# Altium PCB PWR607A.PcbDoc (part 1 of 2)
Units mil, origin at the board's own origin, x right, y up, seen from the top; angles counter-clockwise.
Board outline 5200 x 2850 mil, 4 copper layers (Top Layer, MidLayer1, MidLayer2, Bottom Layer), stack 61.6 mil thick; 153 components, 65 nets, 324 pads, 227 vias.
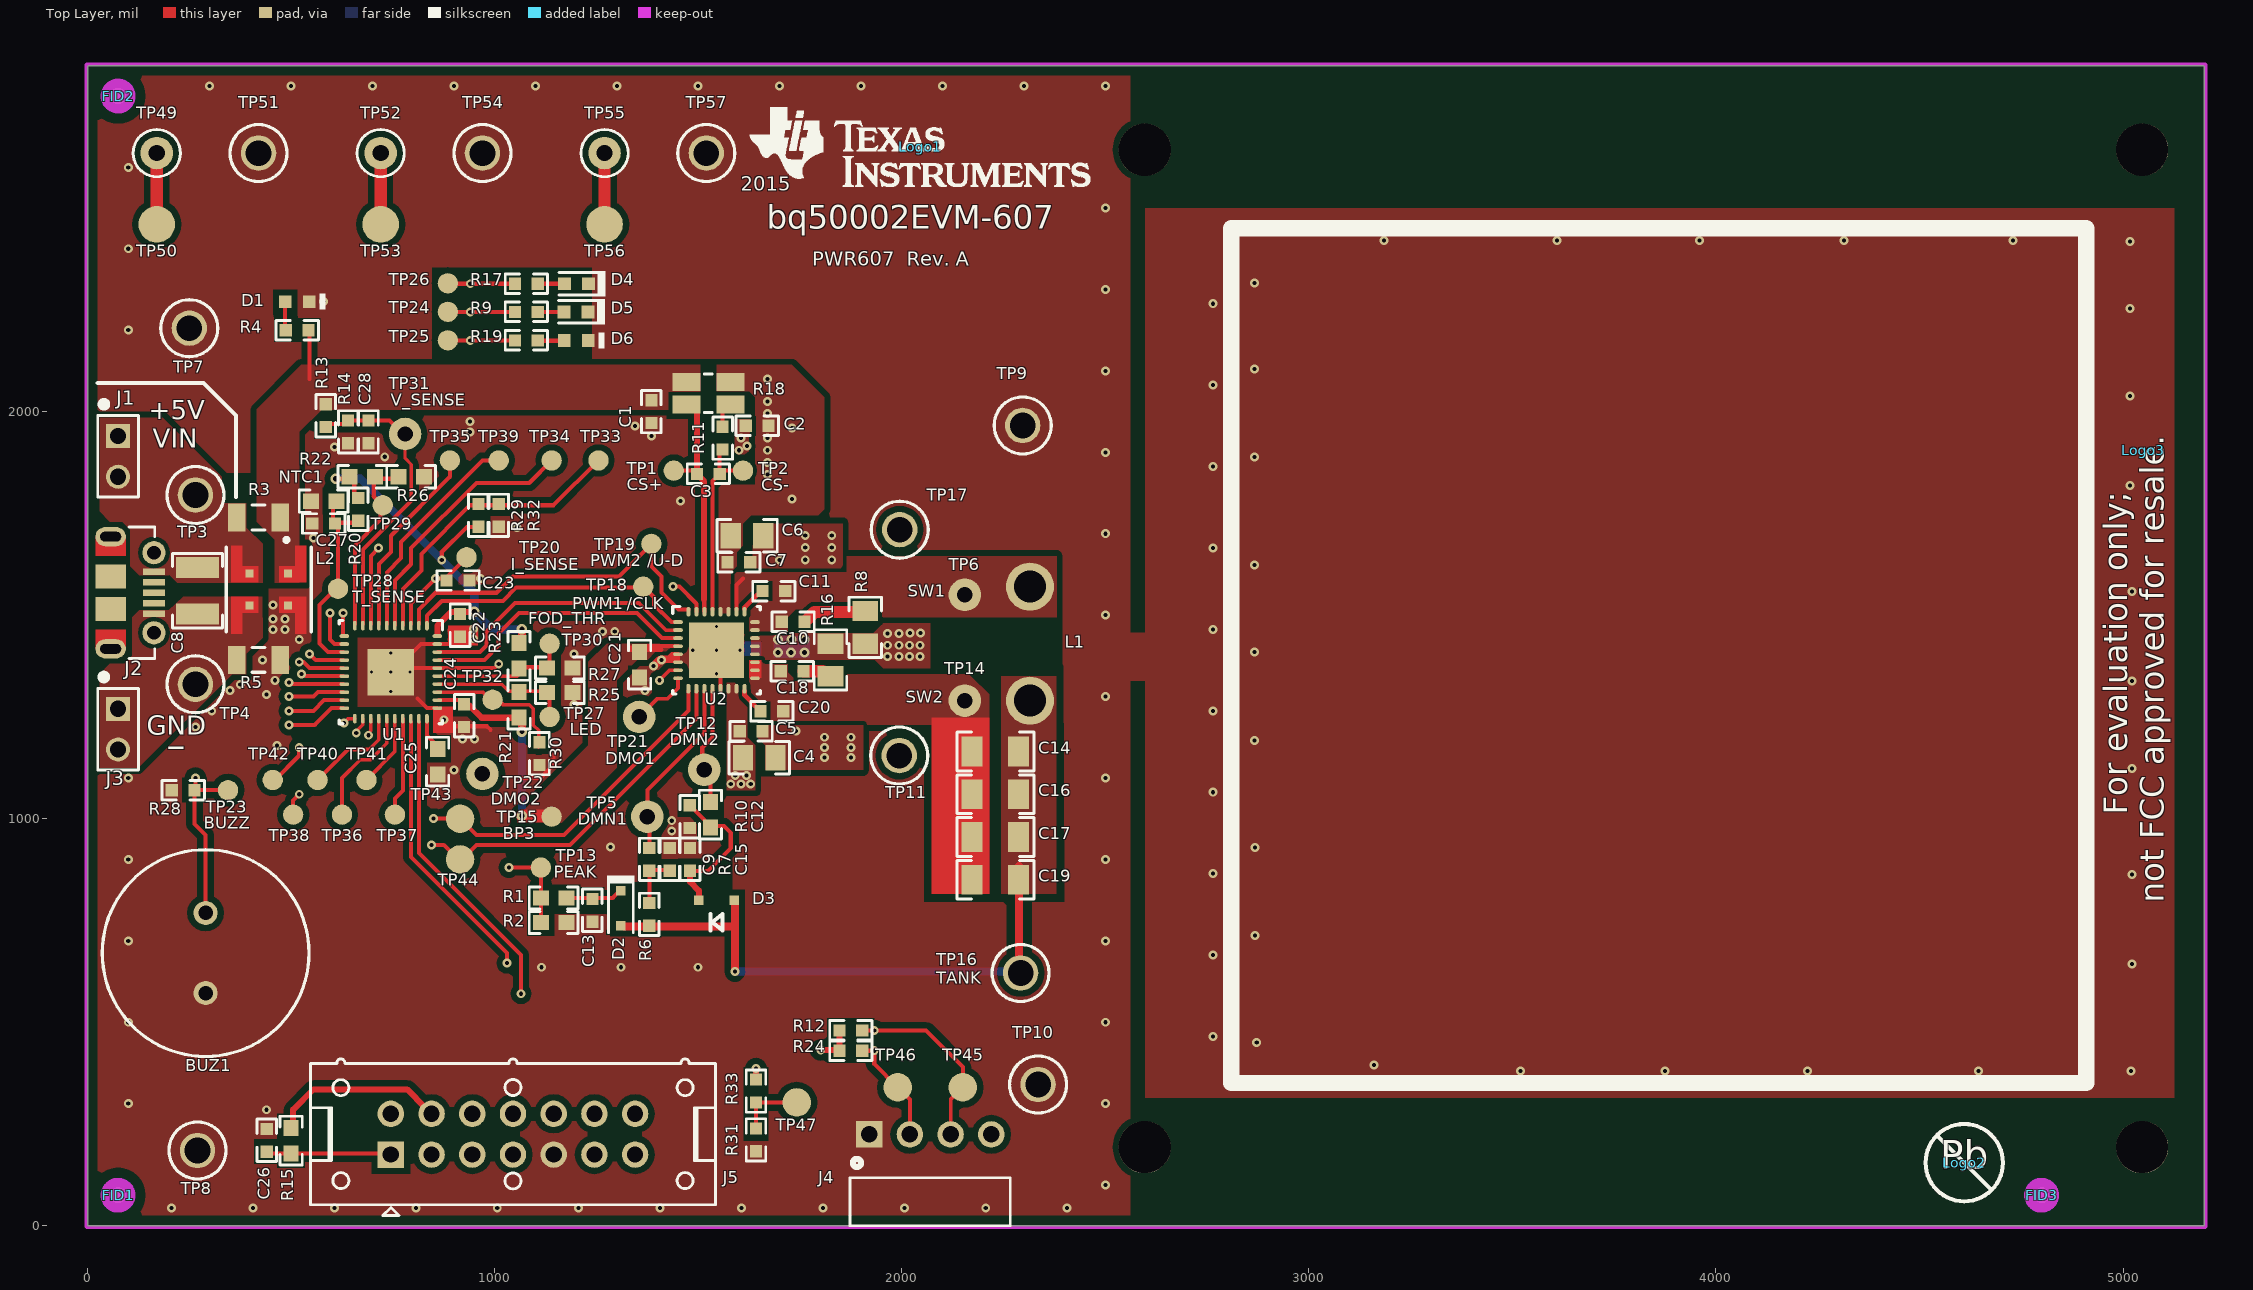
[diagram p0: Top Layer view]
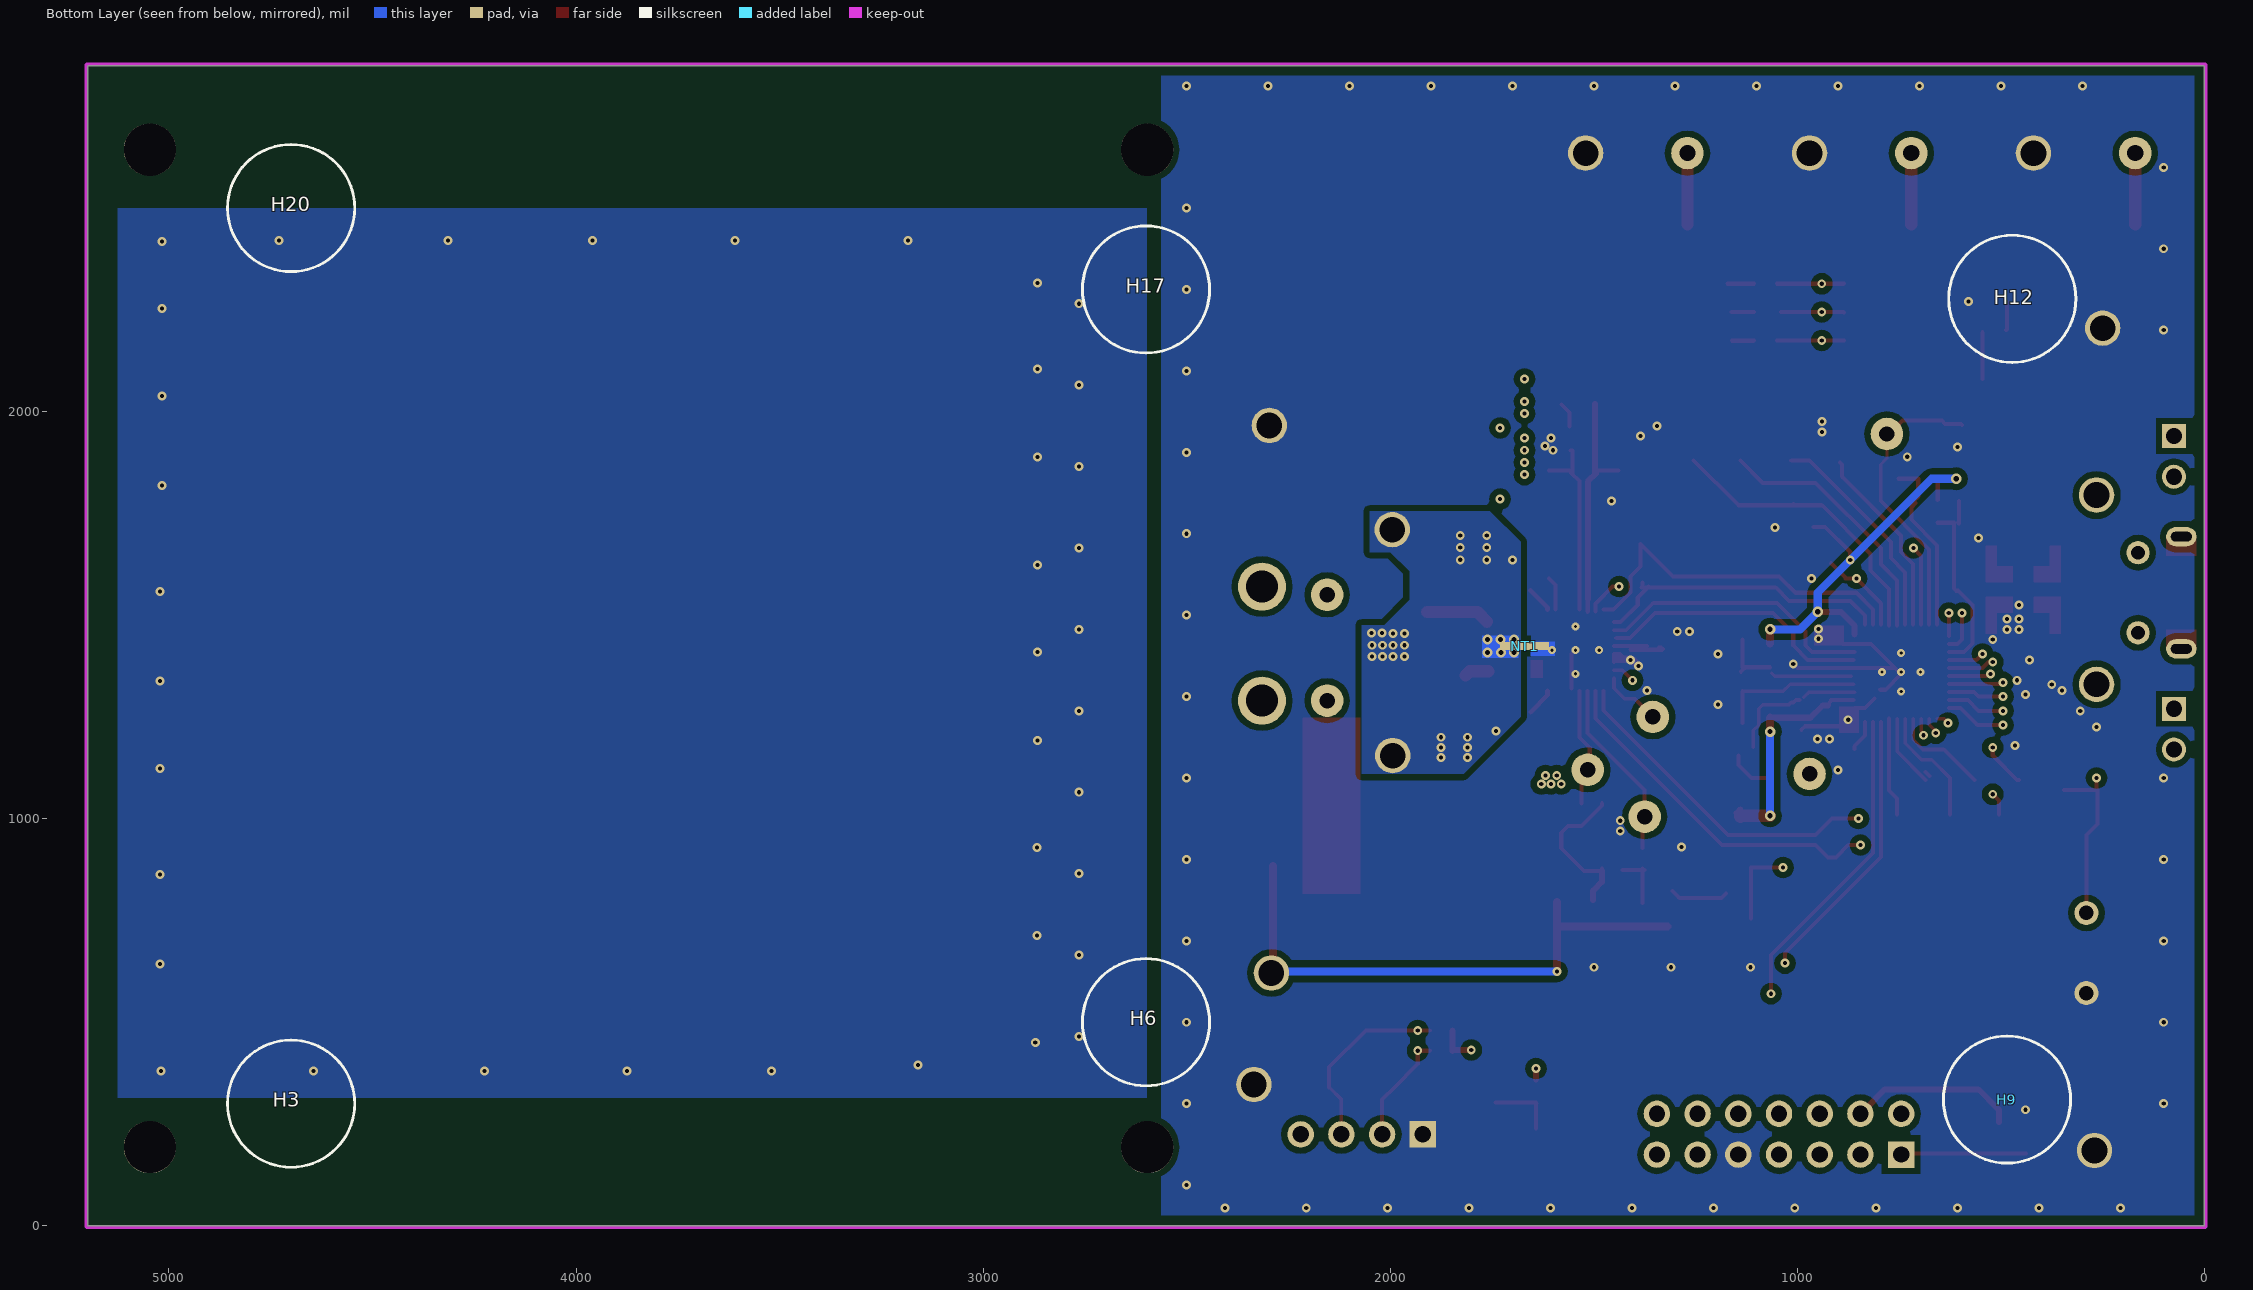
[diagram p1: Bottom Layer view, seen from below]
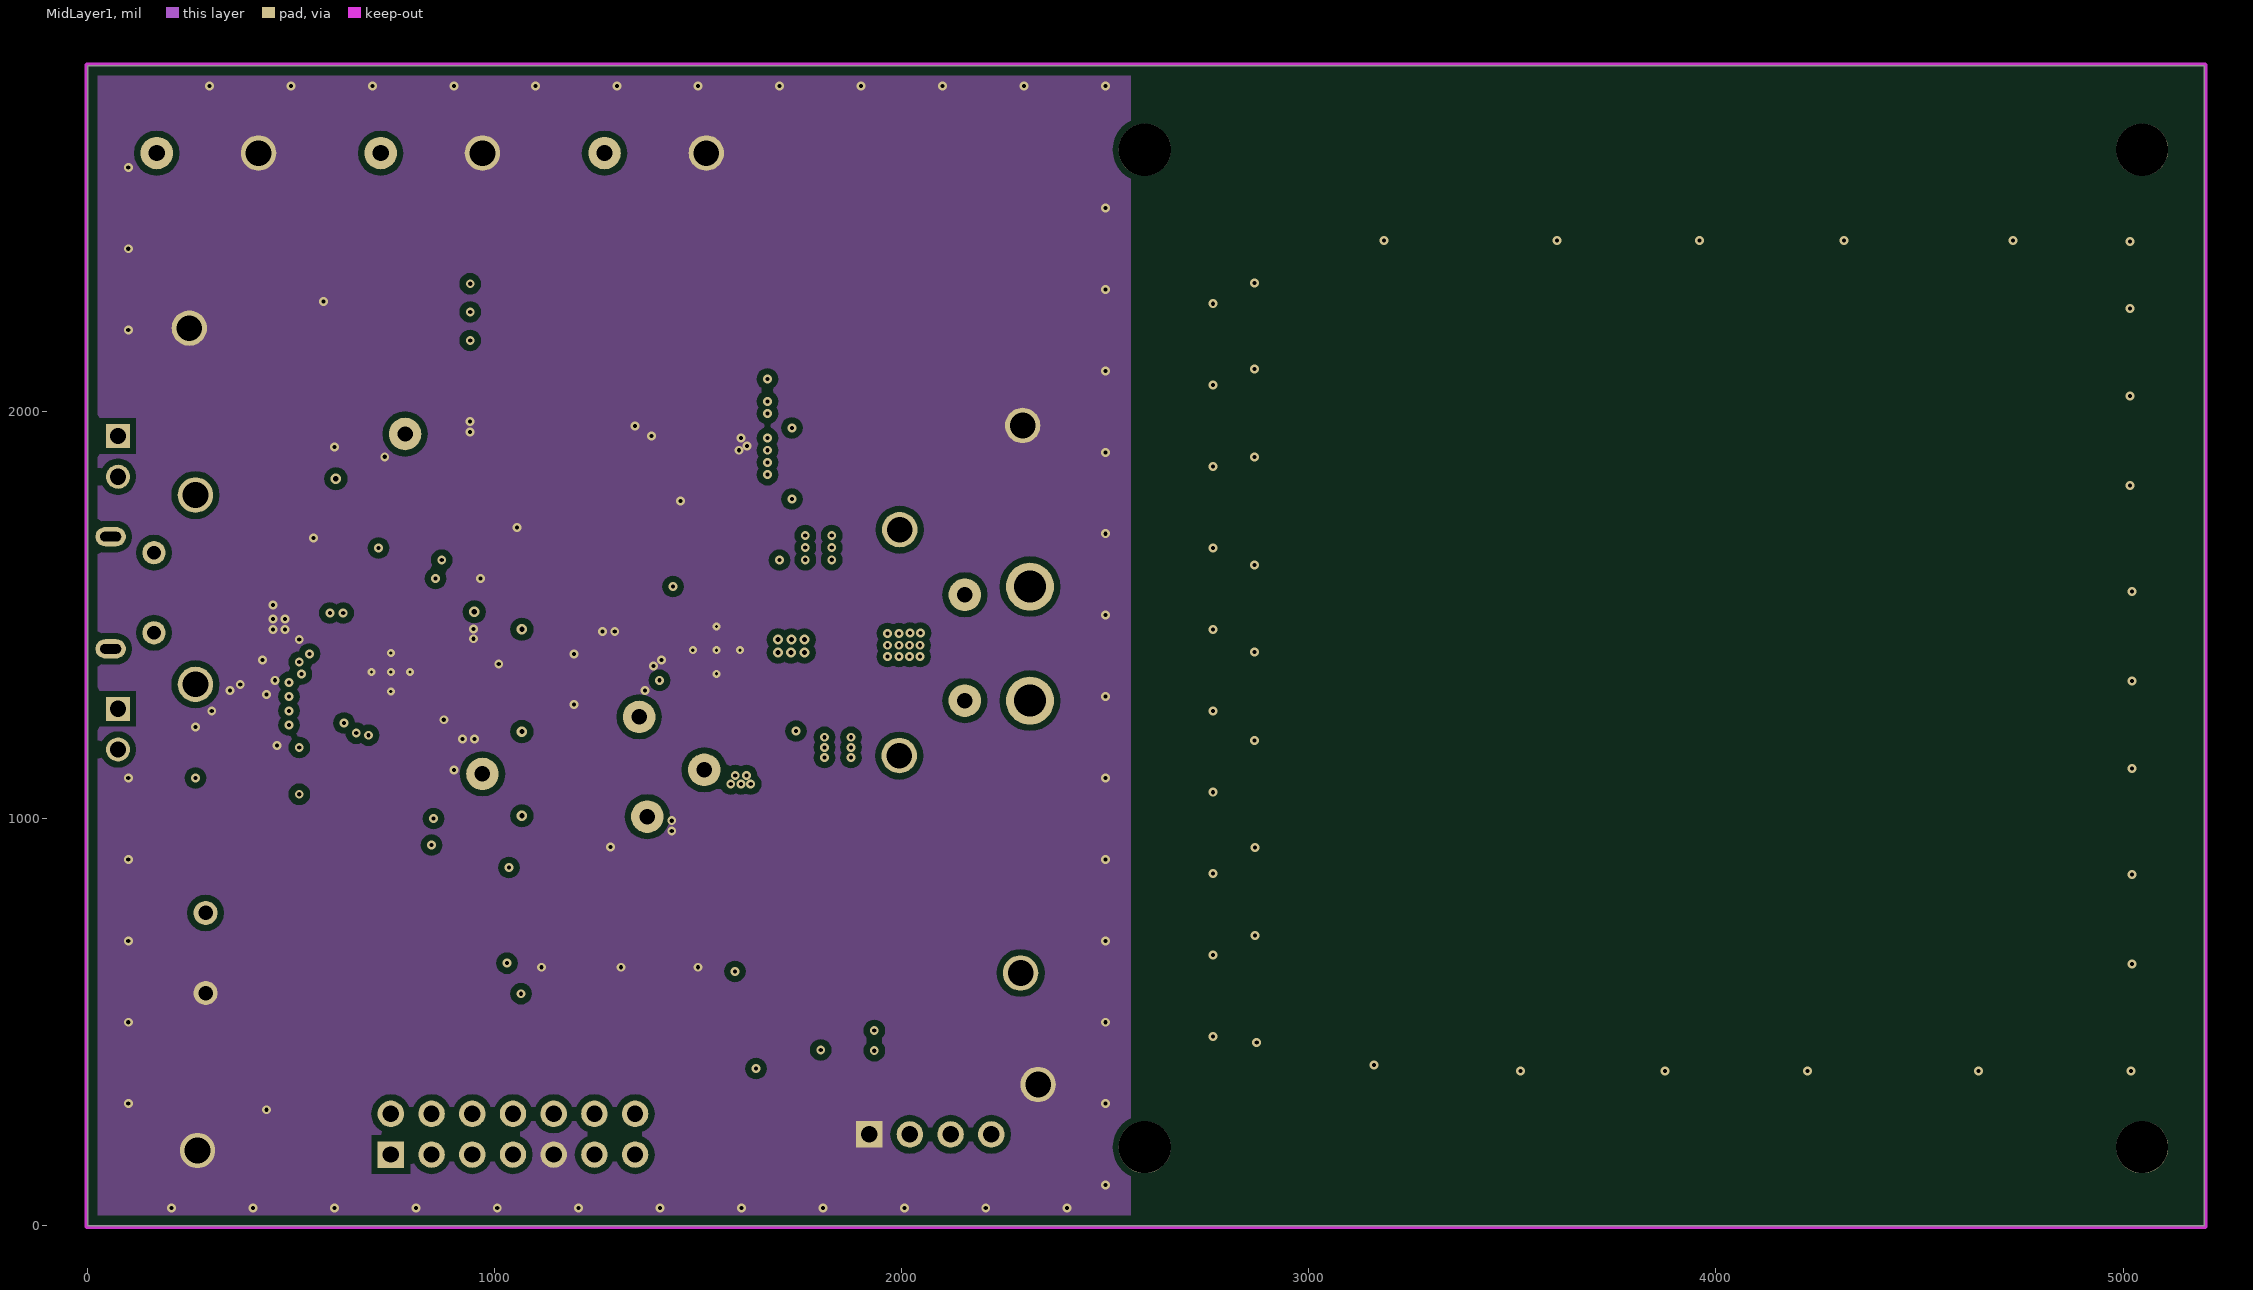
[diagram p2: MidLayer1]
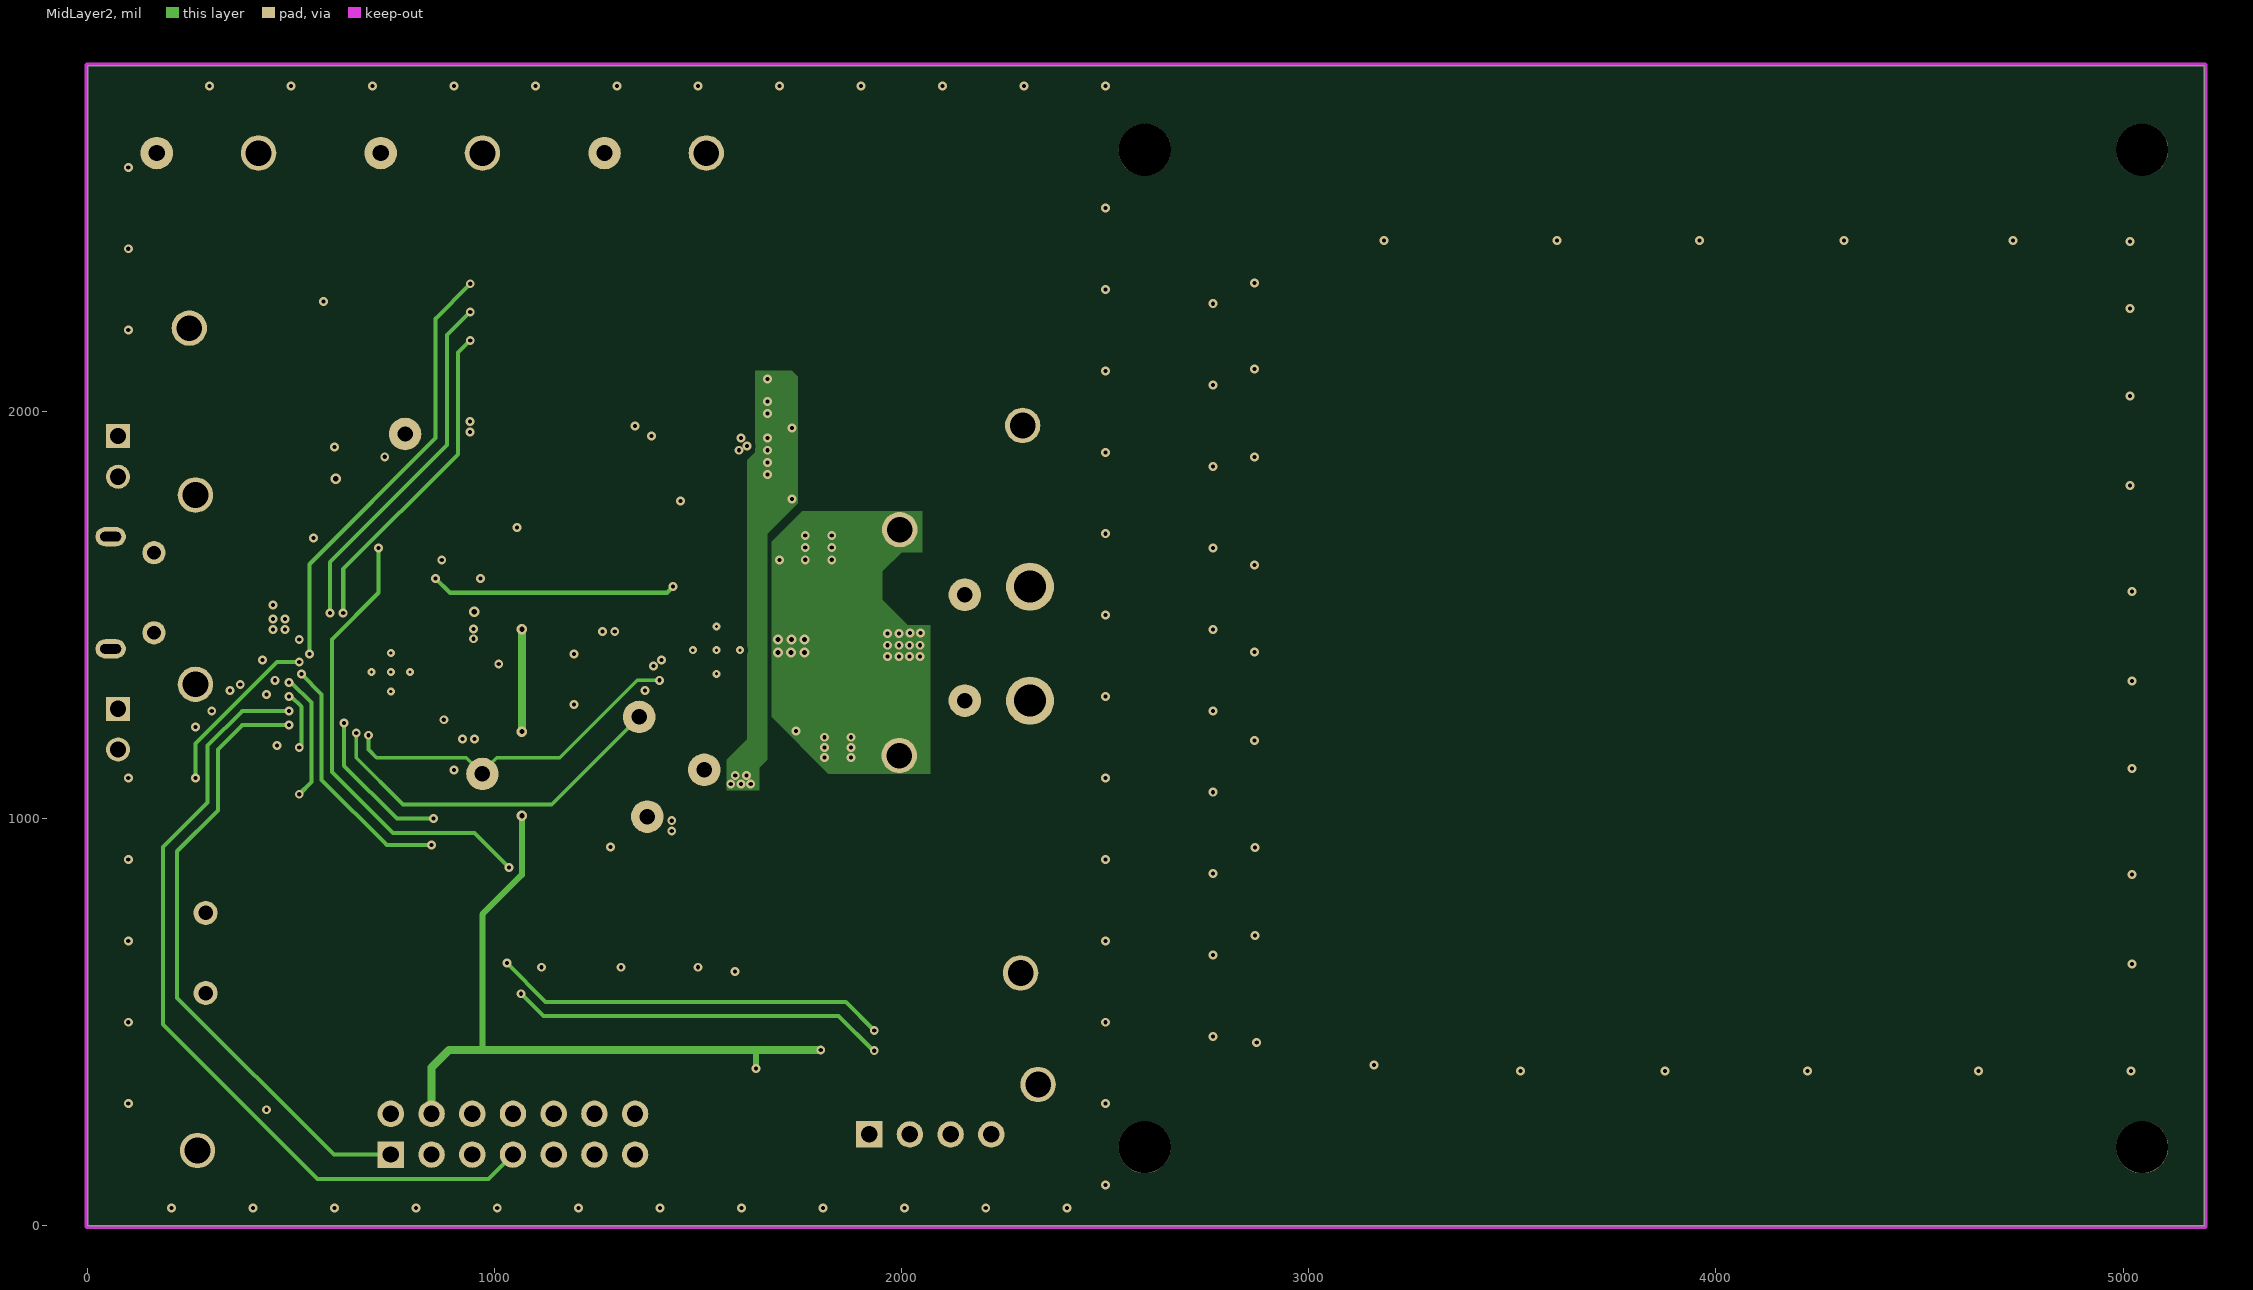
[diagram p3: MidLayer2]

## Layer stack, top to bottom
Top Solder: solder mask 0.4, Solder Resist, Dk 3.5
Top Layer: signal copper 1.4
Dielectric1: core 18, FR-4 High Tg, Dk 4.8
MidLayer1: signal copper 1.4
Dielectric2: prepreg 20, FR-4 High Tg, Dk 4.8
MidLayer2: signal copper 1.4
Dielectric3: core 18, FR-4 High Tg, Dk 4.8
Bottom Layer: signal copper 1.4
Bottom Solder: solder mask 0.4, Solder Resist, Dk 3.5

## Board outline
0,0 0,2850 5200,2850 5200,0

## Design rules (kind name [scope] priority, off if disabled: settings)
AcuteAngle [All] p1: minimum=4.50000000000000E+0001 checktracksonly=FALSE
AssemblyTestPointUsage [All] p1 off: valid=2
AssemblyTestpoint [All] p1 off: testpointundercomponent=TRUE minsize=40 maxsize=100 preferedsize=60 minholesize=0 maxholesize=40 preferedholesize=32 testpointgrid=1 usegrid=TRUE gridtolerance=0.01 allowsidetop=TRUE allowsidebottom=TRUE
Clearance Clearance_J1 [OnCopper and InComponent('J1') vs iskeepout] p1: gap=15
Clearance Clearance_BoardEdge_MountingHoles [OnCopper and InComponentClass('Mounting Holes') vs IsKeepOut] p2: gap=40
Clearance Clearance_BoardEdge_Poly [OnCopper and InPoly vs IsKeepOut] p3: gap=25
Clearance Clearance_BoardEdge [OnCopper and Not InComponentClass('Logo') and not InComponentClass('FiducialMark') and not InRegion(1000,500,4000,800) and Not IsKeepout vs IsKeepOut] p4: gap=25
Clearance Clearance_GND_poly [inpoly and innet('GND')] p5: gap=15
Clearance Clearance_Poly [InPolygon] p6: gap=10
Clearance [All] p7: gap=7.8
ComponentClearance ComponentClearance_Logo [InComponentClass('Logo')] p1 off: gap=50 collisioncheckmode=3 verticalgap=10 showdistances=FALSE
ComponentClearance ComponentClearance_ScrewToNut [(HasFootprint('NY PMS 440 0025 PH')) vs (HasFootprint('Keystone_1902C'))] p2 off: gap=5 collisioncheckmode=3 verticalgap=10 showdistances=FALSE
ComponentClearance ComponentClearance_MountingHoles [InComponentClass('Mounting Holes')] p3 off: gap=250 collisioncheckmode=3 verticalgap=100000 showdistances=FALSE
ComponentClearance ComponentClearance_SmallPassives [HasFootprint('0201*') or HasFootprint('0402*') or HasFootprint('0508') or HasFootprint('0603*') or HasFootprint('0612') or HasFootprint('0805*') or HasFootprint('0815*') or HasFootprint('0830*') or HasFootprint('1206*') or HasFootprint('1210*') or HasFootprint('1808*') or HasFootprint('1812*') or HasFootprint('1825*') or HasFootprint('2010*') or HasFootprint('2220*') or HasFootprint('2225*') or HasFootprint('2512*') or HasFootprint('2728*') or HasFootprint('3518*') vs HasFootprint('0201*') or HasFootprint('0402*') or HasFootprint('0508') or HasFootprint('0603*') or HasFootprint('0612') or HasFootprint('0805*') or HasFootprint('0815*') or HasFootprint('0830*') or HasFootprint('1206*') or HasFootprint('1210*') or HasFootprint('1808*') or HasFootprint('1812*') or HasFootprint('1825*') or HasFootprint('2010*') or HasFootprint('2220*') or HasFootprint('2225*') or HasFootprint('2512*') or HasFootprint('2728*') or HasFootprint('3518*')] p4 off: gap=20 collisioncheckmode=3 verticalgap=10 showdistances=FALSE
ComponentClearance ComponentClearance_THtoSMT [IsThruComponent vs IsSMTComponent] p5 off: gap=100 collisioncheckmode=3 verticalgap=30 showdistances=FALSE
ComponentClearance ComponentClearance_THtoTH [IsThruComponent vs IsThruComponent] p6 off: gap=118.11 collisioncheckmode=3 verticalgap=30 showdistances=FALSE
ComponentClearance [All] p7 off: gap=40 collisioncheckmode=3 verticalgap=10 showdistances=FALSE
DiffPairsRouting [All] p1: maxlimit=100 minlimit=10 mostfreqgap=10 toplayer_minwidth=15 toplayer_maxwidth=15 toplayer_prefwidth=15 midlayer1_minwidth=15 midlayer1_maxwidth=15 midlayer1_prefwidth=15 midlayer2_minwidth=15 midlayer2_maxwidth=15 midlayer2_prefwidth=15 bottomlayer_minwidth=15 bottomlayer_maxwidth=15 bottomlayer_prefwidth=15 maxuncoupledlength=1000
FabricationTestPointUsage TestPointUsage [All] p1 off: valid=2 allowmultiple=FALSE
FabricationTestpoint Testpoint [All] p1 off: side=3 testpointundercomponent=TRUE minsize=40 maxsize=100 preferedsize=60 minholesize=0 maxholesize=40 preferedholesize=32 testpointgrid=1 allowsidetop=TRUE allowsidebottom=TRUE usegrid=TRUE gridtolerance=0.01
FanoutControl Fanout_LCC [IsLCC] p1: bgadir=Out bgaviamode=Centered fanoutstyle=Auto fanoutdirection=Alternating viagrid=1 // Fanout_LCC (Default Rule)
FanoutControl Fanout_BGA [IsBGA] p2: bgadir=Out bgaviamode=Centered fanoutstyle=Auto fanoutdirection=Alternating viagrid=1 // Fanout_BGA (Default Rule)
FanoutControl Fanout_Default [All] p4: bgadir=Out bgaviamode=Centered fanoutstyle=Auto fanoutdirection=Alternating viagrid=1 // Fanout_Default (Default Rule)
FanoutControl Fanout_Small [(CompPinCount < 5)] p5: bgadir=Out bgaviamode=Centered fanoutstyle=Auto fanoutdirection=OutThenIn viagrid=1 // Fanout_Small (Default Rule)
HoleSize [All] p1: absolutevalues=TRUE maxlimit=251 minlimit=7 maxpercent=80.000 minpercent=20.000
MinimumAnnularRing [All] p1: minimumring=5.9
MinimumSolderMaskSliver MinimumSolderMaskSliver_Logo [InComponentClass('Logo') vs InComponentClass('Logo')] p1: minsoldermaskwidth=0.7
MinimumSolderMaskSliver [All] p2: minsoldermaskwidth=3.97
PlaneClearance PlaneClearance_1 [(InNet('TANK') AND InNet('GND'))] p1: clearance=20
PlaneClearance [All] p2: clearance=10
PlaneConnect [(InNet('GND') AND InNet('PGND'))] p1: planeconnectstyle=Direct reliefexpansion=10 reliefentries=4 reliefconductorwidth=10 reliefairgap=10
PolygonConnect [All] p1: connectstyle=Direct reliefconductorwidth=10 reliefentries=4 polygonreliefangle="90 Angle" airgapwidth=10
RoutingVias [All] p1: holewidth=10 width=22 viastyle="Through Hole" minholewidth=7.8 minwidth=19.6 maxholewidth=40 maxwidth=65
SMDToCorner [All] p1: distance=30000
ShortCircuit ShortCircuit_J1_fill [ispad and incomponent('J2') vs isfill] p1: allowed=TRUE
ShortCircuit [All] p2: allowed=FALSE
SilkToBoardRegionClearance [All] p1 off:
SilkToSilkClearance SilkToSilkClearance_logo [InComponentClass('Logo') vs InComponentClass('Logo')] p1: silktosilkclearance=0
SilkToSilkClearance [All] p2: silktosilkclearance=3
SilkToSolderMaskClearance SilkscreenOverComponentPads [IsPad] p1: minsilkscreentomaskgap=3 clearancetoexposedcopper=TRUE
SolderMaskExpansion [All] p1: expansion=1
UnpouredPolygon [All] p1: allowunpoured=FALSE
Width [All] p1: maxlimit=100 minlimit=8 preferedwidth=10 checkconnectedcopper=TRUE
11 further rules are at their usual default settings.

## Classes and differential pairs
component class Header: J1 J3
component class PWR607A_Hardware: !PCB FID1 FID2 FID3 H1 H2 H3 H4 H5 H6 H7 H8 H9 H10 H11 H12 H13 H14 H15 H16 H17 H20 Logo1 Logo2 Logo3 ZZ2 ZZ3 ZZ4 ZZ5 ZZ6 ZZ7
component class Logo: Logo1 Logo2
component class FiducialMark: FID1 FID2 FID3
component class AssemblyNote: ZZ2 ZZ3 ZZ4
component class PWR607A: BUZ1 C1 C2 C3 C4 C5 C6 C7 C8 C9 C10 C11 C12 C13 C14 C15 C16 C17 C18 C19 C20 C21 C22 C23 C24 C25 C26 C27 C28 D1 D2 D3 D4 D5 D6 J1 J2 J3 J4 J5 L1 L2 NT1 NTC1 R1 R2 R3 R4 R5 R6 R7 R8 R9 R10 R11 R12 R13 R14 R15 R16 R17 R18 R19 R20 R21 R22 R23 R24 R25 R26 R27 R28 R29 R30 R31 R32 R33 TP1 TP2 TP3 TP4 TP5 TP6 TP7 TP8 TP9 TP10 TP11 TP12 TP13 TP14 TP15 TP16 TP17 TP18 TP19 TP20 TP21 TP22 TP23 TP24 TP25 TP26 TP27 TP28 TP29 TP30 TP31 TP32 TP33 TP34 TP35 TP36 TP37 TP38 TP39 TP40 TP41 TP42 TP43 TP44 TP45 TP46 TP47 TP49 TP50 TP51 TP52 TP53 TP54 TP55 TP56 TP57 U1 U2

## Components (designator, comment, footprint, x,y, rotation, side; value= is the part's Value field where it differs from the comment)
BUZ1 "PS1240P02CT3" TDK_PS1240P02C 290,670 r270 top
C1 "GRM188R71E105KA12D" 0603_HV 1385,2000 r90 top
C2 "GRM188R71E105KA12D" 0603_HV 1645,1965 r0 top
C3 "GRM188R71A225KE15D" 0603_HV 1525,1847 r0 top
C4 "GRM21BR61E226ME44" 0805_HV 1650,1150 r0 top
C5 "C1608X7R1E104K" 0603_HV 1630,1215 r180 top
C6 "GRM21BR61E226ME44" 0805_HV 1620,1695 r0 top
C7 "C1608X7R1E104K" 0603_HV 1600,1630 r180 top
C8 "GRM32ER71E226KE15L" 1210 270,1560 r270 top
C9 "C1608C0G1H102J" 0603_HV 1380,900 r90 top
C10 "C1608X7R1H473K" 0603_HV 1733,1484 r0 top
C11 "C1608X7R1E104K" 0603_HV 1686,1559 r0 top
C12 "C1608X7R1H223K" 0603 1530,1010 r90 top
C13 "GRM188R71H222KA01D" 0603_HV 1240,775 r270 top
C14 "C3216C0G1E104J" 1206 2230,1165 r180 top
C15 "C1608C0G1H272J" 0603_HV 1480,900 r90 top
C16 "C3216C0G1E104J" 1206 2230,1060 r180 top
C17 "C3216C0G1E104J" 1206 2230,955 r180 top
C18 "C1608X7R1H473K" 0603_HV 1731,1362 r0 top
C19 "C3216C0G1E104J" 1206 2230,850 r180 top
C20 "C1608X7R1E104K" 0603_HV 1681,1264 r180 top
C21 "GRM188R61C225KE15D" 0603 1356,1378.5 r270 top
C22 "C1608X7R1E104K" 0603_HV 915,1475 r270 top
C23 "C1608X7R1E104K" 0603_HV 910,1585 r180 top
C24 "C1608X7R1E104K" 0603_HV 925,1253 r90 top
C25 "GRM188R71A474KA61D" 0603 860,1140 r90 top
C26 "C1608C0G1H102J" 0603_HV 440,210 r90 top
C27 "C1608X7R1E104K" 0603_HV 580,1725 r0 top
C28 "C1608X7R1E104K" 0603_HV 690,1950 r270 top
D1 "LTST-C190KGKT" LED_LTST-C190_G 515,2270 r0 top
D2 "MMDL914-TP" sod-323 1310,780 r270 top
D3 "MMDL914-TP" sod-323 1545,800 r0 top
D4 "LTST-C190KFKT" LED_LTST-C190 1201,2314 r0 top
D5 "LTST-C190CKT" LED_LTST-C190_Red 1200,2245 r0 top
D6 "LTST-C190KGKT" LED_LTST-C190_G 1200.47,2175 r0 top
FID1 "Fiducial" Fiducial10-20 75,75 r0 top
FID2 "Fiducial" Fiducial10-20 75,2775 r0 top
FID3 "Fiducial" Fiducial10-20 4800,75 r0 top
H3 "2563" Bumpon_SJ61A1 4700,300 r180 bottom
H6 "2563" Bumpon_SJ61A1 2600,500 r180 bottom
H9 "2563" Bumpon_SJ61A1 485,310 r180 bottom
H12 "2563" Bumpon_SJ61A1 472,2277 r180 bottom
H17 "2563" Bumpon_SJ61A1 2600,2300 r180 bottom
H20 "2563" Bumpon_SJ61A1 4700,2500 r180 bottom
J1 "PEC02SAAN" CONN_PEC02SAAN 75,1890 r270 top
J2 "105017-0001" CONN_105017-0001 110,1555 r270 top
J3 "PEC02SAAN" CONN_PEC02SAAN 75,1220 r270 top
J4 "22-05-3041" CONN_22-05-3041 2070,0 r0 top
J5 "SBH11-PBPC-D07-ST-BK" CONN_SBH11-PBPC-D07-ST-BK 1045,225 r0 top
L1 "760308111" WE-WPCC_5353_Qi_A11 3860,1405 r270 top locked
L2 "DLW5BTM102TQ2K" DLW5BT_TQ2 445,1562.71 r270 top
Logo1 "Texas Instruments" TI_Stacked_Overlay_Small 2045,2650 r0 top
Logo2 "Pb-Free Symbol" Pb-Free_Overlay_Medium 4610,155 r0 top
Logo3 "FCC disclaimer" FCC_disclaimer_stacked 5050,1905 r90 top
NT1 "Net-Tie" Net-Tie_20milWide_60milLong 1670,1424.13 r0 bottom net-tie
NTC1 "NTCG163JF103F" 0603 580,1780 r0 top
R1 "RG1608P-1133-B-T5" 0603 1145,805 r0 top
R2 "RG1608P-7682-B-T5" 0603 1145,745 r180 top
R3 "CRCW12060000Z0EA" 1206L 420,1740 r0 top
R4 "CRCW06031K00FKEA" 0603_HV 515,2200 r0 top
R5 "CRCW12060000Z0EA" 1206L 420,1390 r0 top
R6 "RC0603FR-0769K8L" 0603_HV 1380,765 r270 top
R7 "RC0603FR-0710KL" 0603_HV 1430,900 r270 top
R8 "ERJ-S6SJR20V" 0805_HV 1910,1470 r90 top
R9 "CRCW06031K00FKEA" 0603_HV 1078,2245 r180 top
R10 "RC0603FR-07499KL" 0603_HV 1479,1005 r90 top
R11 "CRCW06032R00FKEA" 0603_HV 1560,1935 r90 top
R12 "RC0603FR-0710KL" 0603_HV 1875,480 r180 top
R13 "RG1608P-7682-B-T5" 0603_HV 585,1990 r90 top
R14 "RT0603BRD0710KL" 0603_HV 640,1950 r90 top
R15 "RC0603JR-0747KL" 0603 500,209 r90 top
R16 "ERJ-S6SJR20V" 0805_HV 1825,1390 r270 top
R17 "CRCW06031K00FKEA" 0603_HV 1078,2314 r180 top
R18 "LVK12R020DER" LVK12 1525,2045 r0 top
R19 "CRCW06031K00FKEA" 0603_HV 1078,2175 r180 top
R20 "RC0603FR-0710KL" 0603_HV 665,1760 r270 top
R21 "RC0603FR-07100KL" 0603 1060,1280 r270 top
R22 "RC0603FR-07100KL" 0603 675,1840 r180 top
R23 "RC0603FR-07200KL" 0603 1060,1400 r90 top
R24 "RC0603FR-0710KL" 0603_HV 1875,430 r180 top
R25 "RC0603FR-0724K9L" 0603 1160,1310 r180 top
R26 "RC0603FR-0780K6L" 0603 795,1840 r180 top
R27 "RC0603FR-07100KL" 0603 1160,1370 r180 top
R28 "RC0603FR-0710KL" 0603_HV 235,1070 r0 top
R29 "RC0603FR-0710KL" 0603_HV 960,1745 r90 top
R30 "RC0603FR-0710KL" 0603_HV 1110,1160 r270 top
R31 "RC0603FR-0710KL" 0603_HV 1642,211 r270 top
R32 "RC0603FR-0710KL" 0603_HV 1010,1745 r90 top
R33 "RC0603FR-0710KL" 0603_HV 1642,331 r270 top
TP1 "Pogo Pad" PogoPad#1 1440,1855 r90 top
TP2 "Pogo Pad" PogoPad#1 1610,1855 r90 top
TP3 "5005" Keystone5005 265,1795 r0 top
TP4 "5011" Keystone5011 265,1330 r180 top
TP5 "PartNumber" TESTPOINT 1375,1005 r0 top
TP6 "PartNumber" TESTPOINT 2155,1550 r180 top
TP7 "5011" Keystone5011 250,2205 r0 top
TP8 "5011" Keystone5011 270,185 r0 top
TP9 "5011" Keystone5011 2297,1966 r0 top
TP10 "5011" Keystone5011 2335,347 r0 top
TP11 "5011" Keystone5011 1994,1155 r90 top
TP12 "PartNumber" TESTPOINT 1515,1120 r0 top
TP13 "Pogo Pad" PogoPad#1 1113.5,880 r0 top
TP14 "PartNumber" TESTPOINT 2155,1290 r90 top
TP15 "Pogo Pad" PogoPad#1 1140,1005 r90 top
TP16 "5007" Keystone5007 2292,621 r0 top
TP17 "5011" Keystone5011 1995,1710 r90 top
TP18 "Pogo Pad" PogoPad#1 1365,1570 r90 top
TP19 "Pogo Pad" PogoPad#1 1385,1675 r90 top
TP20 "Pogo Pad" PogoPad#1 931,1642 r0 top
TP21 "PartNumber" TESTPOINT 1355,1250 r0 top
TP22 "PartNumber" TESTPOINT 970,1110 r0 top
TP23 "Pogo Pad" PogoPad#1 345,1070 r0 top
TP24 "Pogo Pad" PogoPad#1 885,2245 r90 top
TP25 "Pogo Pad" PogoPad#1 885,2175 r90 top
TP26 "Pogo Pad" PogoPad#1 885,2315 r90 top
TP27 "Pogo Pad" PogoPad#1 1135,1250 r0 top
TP28 "Pogo Pad" PogoPad#1 615,1565 r0 top
TP29 "Pogo Pad" PogoPad#1 725,1770 r0 top
TP30 "Pogo Pad" PogoPad#1 1135,1430 r0 top
TP31 "PartNumber" TESTPOINT 780,1945 r0 top
TP32 "Pogo Pad" PogoPad#1 995,1292 r90 top
TP33 "Pogo Pad" PogoPad#1 1255,1880 r90 top
TP34 "Pogo Pad" PogoPad#1 1140,1880 r0 top
TP35 "Pogo Pad" PogoPad#1 890,1880 r0 top
TP36 "Pogo Pad" PogoPad#1 625,1010 r0 top
TP37 "Pogo Pad" PogoPad#1 755,1010 r0 top
TP38 "Pogo Pad" PogoPad#1 505,1010 r90 top
TP39 "Pogo Pad" PogoPad#1 1010,1880 r0 top
TP40 "Pogo Pad" PogoPad#1 565,1095 r0 top
TP41 "Pogo Pad" PogoPad#1 685,1095 r0 top
TP42 "Pogo Pad" PogoPad#1 455,1095 r90 top
TP43 "Pogo Pad" PogoPad#2 915,1000 r90 top
TP44 "Pogo Pad" PogoPad#2 915,900 r90 top
TP45 "Pogo Pad" PogoPad#2 2150,340 r90 top
TP46 "Pogo Pad" PogoPad#2 1990,340 r90 top
TP47 "Pogo Pad" PogoPad#2 1742,303 r90 top
TP49 "5002" Keystone5002 170,2635 r90 top
TP50 "Pogo Pad" PogoPad#3 170,2460 r90 top locked
TP51 "5011" Keystone5011 420,2635 r0 top
TP52 "5002" Keystone5002 720,2635 r90 top
TP53 "Pogo Pad" PogoPad#3 720,2460 r90 top locked
TP54 "5011" Keystone5011 970,2635 r0 top
TP55 "5002" Keystone5002 1270,2635 r90 top
TP56 "Pogo Pad" PogoPad#3 1270,2460 r0 top locked
TP57 "5011" Keystone5011 1520,2635 r0 top
U1 "BQ500511RHAR" RHA0040A 745,1360 r270 top
U2 "BQ50002RHB" RHB0032E 1544.9,1413.9 r0 top
ZZ2 "These assemblies are ESD sensitive, ESD precautions shall be observed." AssemblyNote 200,3517 r0 top
ZZ3 "These assemblies must be clean and free from flux and all contaminants. Use of no clean flux is not acceptable." AssemblyNote 200,3430 r0 top
ZZ4 "These assemblies must comply with workmanship standards IPC-A-610 Class 2., unless otherwise specified." AssemblyNote 200,3350 r0 top
ZZ5 "If Sil-Pad part number GP1500-0.020-00-0404 is used, the pads need to be cut into 2 inch squares." AssemblyNote 200,3265 r0 top
ZZ6 "Apply thin layer of SA-1000 between Aluminum Plate MCH003 and PCB during installation" AssemblyNote 200,3185 r0 top
ZZ7 "See PWR045 Assembly Guide for build up on L1 and associated hardware" AssemblyNote 200,3105 r0 top

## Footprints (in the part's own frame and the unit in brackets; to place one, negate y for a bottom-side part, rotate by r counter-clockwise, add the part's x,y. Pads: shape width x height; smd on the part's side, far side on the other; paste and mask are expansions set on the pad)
0603 [mm] "0603 from SM-752 data"
  rect 1x0.95 smd: 1(-0.8,0) 2(0.8,0)
  silkscreen extent -1.52,-0.69 1.52,0.69, body extent -0.87,-0.47 0.87,0.47, height 0.85
0603_HV [mil] "Ernesto recommended land pattern.  26 mil between pads."
  rect 30x30 smd: 1(-28,0) 2(28,0)
  silkscreen extent -52,-24 52,24, body extent -34,-19 34,19, height 33
0805_HV [mil] "0805 with 30mil clearance between pads"
  rect 50x63 smd: 1(-40,0) 2(40,0)
  silkscreen extent -74,-40 74,40, body extent -43,-29 43,29, height 43
1206 [mm] "1206 from SM-752 data"
  rect 1.3x1.85 smd: 1(-1.45,0) 2(1.45,0)
  silkscreen extent -2.4,-1.21 2.4,1.21, body extent -1.7,-0.9 1.7,0.9, height 1.35
1206L [mm] "1206 from SM-752 data"
  rect 1.1x1.75 smd: 1(-1.35,0) 2(1.35,0)
  silkscreen extent -0.4,-0.77 0.4,0.77, body extent -1.7,-0.9 1.7,0.9, height 1.35
1210 [mm] "1210 from SM-752 data"
  rect 1.3x2.7 smd: 1(-1.45,0) 2(1.45,0)
  silkscreen extent -2.32,-1.57 2.32,1.57, body extent -1.7,-1.35 1.7,1.35, height 1.35
AssemblyNote [mil] "Assembly Note"
Bumpon_SJ61A1 [mil] "3M Cylindrical Bumpon black"
  round 1 on Mech4: 0(0,0)
  silkscreen extent -156,-156 156,156, body extent -156,-155 156,156, height 201
CONN_22-05-3041 [mm] "MOLEX"
  rect 1.65x1.65 hole 1.02: 1(-3.81,5.7)
  round 1.65 hole 1.02: 2(-1.27,5.7) 3(1.27,5.7) 4(3.81,5.7)
  silkscreen extent -5,0 5,4.18, body extent -5,-6.91 5,6.02, height 6.37
CONN_105017-0001 [mm] "Molex Micro USB-B"
  rect 0.4x1.35 smd mask+0.051: 1(-1.3,1.35) 2(-0.65,1.35) 3(0,1.35) 4(0.65,1.35) 5(1.3,1.35)
  oval 1.2x1.9 hole 0.6 slot 1.3 at 90 deg: 6(-3.5,-1.35) 9(3.5,-1.35)
  rect 1.5x1.9 smd: 7(-1,-1.35) 8(1,-1.35)
  round 1.45 hole 0.85: 10(2.5,1.35) 11(-2.5,1.35)
  Top Layer region: 3.5,-0.4 2.3,-0.4 2.3,-2.3 3.5,-2.3
  Top Layer region: -3.5,-2.3 -2.3,-2.3 -2.3,-0.4 -3.5,-0.4
  silkscreen extent -4.1,-0.2 4.1,1.4, body extent -4.1,-3.93 4.1,1.5, height 2.72
CONN_PEC02SAAN [mm] "SULLINS"
  rect 1.5x1.5 hole 1.016: 1(-1.27,0)
  round 1.5 hole 1.016: 2(1.27,0)
  silkscreen extent -3.45,-1.27 2.54,1.27, body extent -2.54,-1.27 2.54,1.27, height 8.38
CONN_SBH11-PBPC-D07-ST-BK [mm] "Sullins recommended land pattern"
  rect 1.65x1.65 hole 1.016 mask+0: 1(-7.62,-1.27)
  round 1.65 hole 1.016 mask+0: 2(-7.62,1.27) 3(-5.08,-1.27) 4(-5.08,1.27) 5(-2.54,-1.27) 6(-2.54,1.27) 7(0,-1.27) 8(0,1.27) 9(2.54,-1.27) 10(2.54,1.27) 11(5.08,-1.27) 12(5.08,1.27) 13(7.62,-1.27) 14(7.62,1.27)
  silkscreen extent -12.64,-5.08 12.64,4.7, body extent -12.64,-4.4 12.64,4.7, height 9.12
DLW5BT_TQ2 [mm] "SMD, 4-Leads, Body 5x5mm"
  rect 0.5x0.5 smd: 1(-1,1.2) 2(-1,-1.2) 3(1,-1.2) 4(1,1.2)
  Top Layer region: 0.45,-2.35 0.45,-0.65 1.45,-0.65 1.45,-1.65 2.75,-1.65 2.75,-2.35
  Top Layer region: -0.45,-2.35 -0.45,-0.65 -1.45,-0.65 -1.45,-1.65 -2.75,-1.65 -2.75,-2.35
  Top Layer region: 0.45,2.35 0.45,0.65 1.45,0.65 1.45,1.65 2.75,1.65 2.75,2.35
  Top Layer region: -0.45,2.35 -0.45,0.65 -1.45,0.65 -1.45,1.65 -2.75,1.65 -2.75,2.35
  silkscreen extent -3.22,-2.65 2.65,2.65, body extent -2.65,-2.65 2.65,2.65, height 2.51
FCC_disclaimer_stacked [mil]
Fiducial10-20 [mm]
  round 1 smd mask+0.5: 1(0,0)
  Top Layer keep-out circle w1.178: c0,0 r0.5
Keystone5002 [mil] "For Keystone 500x miniature loop terminals"
  round 80 hole 40: 1(0,0)
  silkscreen extent -58,-58 58,58, body extent -49,-49 49,49, height 182
Keystone5005 [mil] "Keystone Compact loops"
  round 87 hole 63: 1(0,0)
  silkscreen extent -70,-70 70,70, body extent -63,-63 62,63, height 225
Keystone5007 [mil] "Keystone Compact loops"
  round 87 hole 63: 1(0,0)
  silkscreen extent -70,-70 70,70, body extent -63,-63 62,63, height 225
Keystone5011 [mil] "Keystone Multipurpose loops"
  round 87 hole 63: 1(0,0)
  silkscreen extent -70,-70 70,70, body extent -63,-63 63,62, height 319
LED_LTST-C190 [mm] "Lite-On"
  rect 0.8x0.8 smd: 1(-0.75,0) 2(0.75,0)
  silkscreen extent -1.1,-0.8 1.8,0.8, body extent -0.85,-0.45 0.85,0.45, height 0.9
LED_LTST-C190_G [mm] "Lite-On"
  rect 0.8x0.8 smd: 1(-0.75,0) 2(0.75,0)
  silkscreen extent 1.37,-0.5 1.75,0.5, body extent -0.85,-0.45 0.85,0.45, height 0.9
LED_LTST-C190_Red [mm] "Lite-On"
  rect 0.8x0.8 smd: 1(-0.75,0) 2(0.75,0)
  silkscreen extent -1.1,-0.8 1.8,0.8, body extent -0.85,-0.45 0.85,0.45, height 0.9
LVK12 [mm] "Ohmite"
  rect 1.75x1.1 smd: 1(-1.375,0.7) 2(1.375,0.7) 3(-1.375,-0.7) 4(1.375,-0.7)
  silkscreen extent -0.25,-1.2 0.25,1.2, body extent -1.7,-0.9 1.7,0.9, height 0.65
Net-Tie_20milWide_60milLong [mil] "20mil net tie, no solder mask opening, no solder paste"
  rect 60x20 smd paste-10 mask-10: 1(-30,0) 2(30,0)
Pb-Free_Overlay_Medium [mil]
  silkscreen extent -95,-95 95,95
PogoPad#1 [mil] "No Solder Paste"
  round 50 smd paste-35: 1(0,0)
PogoPad#2 [mil] "No Solder Paste"
  round 70 smd paste-35: 1(0,0)
PogoPad#3 [mil] "No Solder Paste"
  round 90 smd paste-45: 1(0,0)
RHA0040A [mm] "QFN, 40-Leads, Body 6x6mm, Pitch 0.5mm, Thermal Pad 2.9x2.9mm, TI Recommended"
  oval 0.6x0.23 smd mask+0.07: 1(-2.9,2.25) 2(-2.9,1.75) 3(-2.9,1.25) 4(-2.9,0.75) 5(-2.9,0.25) 6(-2.9,-0.25) 7(-2.9,-0.75) 8(-2.9,-1.25) 9(-2.9,-1.75) 10(-2.9,-2.25) 21(2.9,-2.25) 22(2.9,-1.75) 23(2.9,-1.25) 24(2.9,-0.75) 25(2.9,-0.25) 26(2.9,0.25) 27(2.9,0.75) 28(2.9,1.25) 29(2.9,1.75) 30(2.9,2.25)
  oval 0.23x0.6 smd mask+0.07: 11(-2.25,-2.9) 12(-1.75,-2.9) 13(-1.25,-2.9) 14(-0.75,-2.9) 15(-0.25,-2.9) 16(0.25,-2.9) 17(0.75,-2.9) 18(1.25,-2.9) 19(1.75,-2.9) 20(2.25,-2.9) 31(2.25,2.9) 32(1.75,2.9) 33(1.25,2.9) 34(0.75,2.9) 35(0.25,2.9) 36(-0.25,2.9) 37(-0.75,2.9) 38(-1.25,2.9) 39(-1.75,2.9) 40(-2.25,2.9)
  rect 2.9x2.9 smd paste-2.45: 41(0,0)
  silkscreen extent -3.22,-3.22 3.22,3.22, body extent -3.08,-3.08 3.08,3.08, height 1.01
RHB0032E [mm] "QFN, 32-Leads, Body 5x5mm, Pitch 0.5mm, Thermal Pad 3.45x3.45mm, TI Recommended"
  oval 0.6x0.24 smd: 1(-2.4,1.75) 2(-2.4,1.25) 3(-2.4,0.75) 4(-2.4,0.25) 5(-2.4,-0.25) 6(-2.4,-0.75) 7(-2.4,-1.25) 8(-2.4,-1.75) 17(2.4,-1.75) 18(2.4,-1.25) 19(2.4,-0.75) 20(2.4,-0.25) 21(2.4,0.25) 22(2.4,0.75) 23(2.4,1.25) 24(2.4,1.75)
  oval 0.24x0.6 smd: 9(-1.75,-2.4) 10(-1.25,-2.4) 11(-0.75,-2.4) 12(-0.25,-2.4) 13(0.25,-2.4) 14(0.75,-2.4) 15(1.25,-2.4) 16(1.75,-2.4) 25(1.75,2.4) 26(1.25,2.4) 27(0.75,2.4) 28(0.25,2.4) 29(-0.25,2.4) 30(-0.75,2.4) 31(-1.25,2.4) 32(-1.75,2.4)
  rect 3.45x3.45 smd paste-1.725: 33(0,0)
  silkscreen extent -2.72,-2.73 2.72,2.73, body extent -2.57,-2.57 2.58,2.58, height 1.01
sod-323 [mm] "NXP recommended land pattern"
  rect 0.6x0.6 smd paste-0.05: 1(-1.1,0) 2(1.1,0)
  silkscreen extent -2.06,-0.86 1.53,0.86, body extent -1.3,-0.67 1.3,0.68, height 1.1
TDK_PS1240P02C [mm] "TDK"
  round 1.5 hole 0.9: 1(-2.5,0) 2(2.5,0)
  silkscreen extent -6.45,-6.45 6.45,6.45, body extent -6.36,-6.36 6.36,6.36, height 4.6
TESTPOINT [mil]
  round 80 hole 37.99: 1(0,0)
TI_Stacked_Overlay_Small [mil]
  silkscreen extent -418,-98 418,98
WE-WPCC_5353_Qi_A11 [mm] "WURTH"
  round 3 hole 2: 1(-4.191,-39.243) 2(2.921,-39.243)
  body extent -25.51,-40.34 25.51,25.51, height 6

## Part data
BUZ1: "Buzzer, Piezo, 4kHz, 12.2mm, TH"
C1 C2: "CAP, CERM, 1 µF, 25 V, +/- 10%, X7R, 0603"
C3: "CAP, CERM, 2.2 µF, 10 V, +/- 10%, X7R, 0603"
C4 C6: "CAP, CERM, 22uF, 25V, +/-20%, X5R, 0805"
C5 C7 C11 C20 C22 C23 C24 C27 C28: "CAP, CERM, 0.1uF, 25V, +/-10%, X7R, 0603"
C8: "CAP, CERM, 22uF, 25V, +/-10%, X7R, 1210"
C9 C26: "CAP, CERM, 1000pF, 50V, +/-5%, C0G/NP0, 0603"
C10 C18: "CAP, CERM, 0.047uF, 50V, +/-10%, X7R, 0603"
C12: "CAP, CERM, 0.022 µF, 50 V, +/- 10%, X7R, 0603"
C13: "CAP, CERM, 2200 pF, 50 V, +/- 10%, X7R, 0603"
C14 C16 C17 C19: "CAP, CERM, 0.1 µF, 25 V, +/- 5%, C0G/NP0, 1206"
C15: "CAP, CERM, 2700pF, 50V, +/-5%, C0G/NP0, 0603"
C21: "CAP, CERM, 2.2uF, 16V, +/-10%, X5R, 0603"
C25: "CAP, CERM, 0.47uF, 10V, +/-10%, X7R, 0603"
D1 D6: "LED, Green, SMD"
D2 D3: "Diode, Switching, 100V, 0.2A, SOD-323"
D4: "LED, Orange, SMD"
D5: "LED, Red, SMD"
FID1 FID2 FID3: "Fiducial mark.  There is nothing to buy or mount."
H3 H6 H9 H12 H17 H20: library part SJ61A1, "Mounting Feet, 0.25\" tall"
J1 J3: "Header, 100mil, 2x1, Tin, TH"
J2: "Receptacle, Micro-USB-B, Right Angle, SMD"
J4: "Header (friction lock), 100mil, 4x1, R/A, TH"
J5: "Header (shrouded), 100 mil, 7x2, Gold plated, TH"
L1: "Inductor, 6.3 µH, 13 A, 0.017 ohm, TH"
L2: "Coupled inductor, 2.5 A, 0.034 ohm, SMD"
Logo1: library part TI_Logo, "Texas Instrument Corporate Signature"
Logo2: library part Pb-Free
Logo3: library part FCC_disclaimer, "FCC_disclaimer"
NT1: "Single point connection between nets."
NTC1: "Thermistor NTC, 10.0k ohm, 1%, 0603"
R1: "RES, 113 k, 0.1%, 0.1 W, 0603"
R2 R13: "RES, 76.8 k, 0.1%, 0.1 W, 0603"
R3 R5: "RES, 0 ohm, 5%, 0.25W, 1206"
R4 R9 R17 R19: "RES, 1.00 k, 1%, 0.1 W, 0603"
R6: "RES, 69.8k ohm, 1%, 0.1W, 0603"
R7 R12 R20 R24 R28 R29 R30 R31 R32 R33: "RES, 10.0k ohm, 1%, 0.1W, 0603"
R8 R16: library part CRM0805-FX-R510ELF, "RES, 0.2 ohm, 5%, 0.25W, 0805"
R10: "RES, 499k ohm, 1%, 0.1W, 0603"
R11: "RES, 2.00, 1%, 0.1 W, 0603"
R14: "RES, 10.0 k, 0.1%, 0.1 W, 0603"
R15: "RES, 47k ohm, 5%, 0.1W, 0603"
R18: "RES, 0.02, 0.5%, 0.5 W, 1206 sense"
R21 R22 R27: "RES, 100 k, 1%, 0.1 W, 0603"
R23: "RES, 200 k, 1%, 0.1 W, 0603"
R25: "RES, 24.9 k, 1%, 0.1 W, 0603"
R26: "RES, 80.6 k, 1%, 0.1 W, 0603"
TP1 TP2 TP13 TP15 TP18 TP19 TP20 TP23 TP24 TP25 TP26 TP27 TP28 TP29 TP30 TP32 TP33 TP34 TP35 TP36 TP37 TP38 TP39 TP40 TP41 TP42 TP43 TP44 TP45 TP46 TP47 TP50 TP53 TP56: library part Pogopad, "Pad for Pogo Pin Connector"
TP3: "Test Point, Compact, Red, TH"
TP4 TP7 TP8 TP9 TP10 TP11 TP17 TP51 TP54 TP57: "Test Point, Multipurpose, Black, TH"
TP5 TP6 TP12 TP14 TP21 TP22 TP31: library part TESTPOINT, "TEST POINT.  No entry in BOM."
TP16: "Test Point, Compact, White, TH"
TP49 TP52 TP55: "Test Point, Miniature, White, TH"
U1: "BQ500511RHA, RHA0040A"
U2: "4.2V to 5.5V Input, 3A Full Bridge, 2 Channel Analog Demodulation Wireless Power TX-Driver for Wireless Charging Applications, RHB0032E"
ZZ2 ZZ3 ZZ4: library part AssemblyNote
ZZ5 ZZ6 ZZ7: library part "Assembly Note"

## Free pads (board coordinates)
  round 128 hole 128: 0(2596.9,193.1) 0(2596.9,2643.1) 0(5046.9,193.1) 0(5046.9,2643.1)

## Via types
v1: diameter 22, hole 10, Top Layer to Bottom Layer, tented both sides, 140 vias
v2: diameter 22/22/22/22 (per signal layer), hole 10, Top Layer to Bottom Layer, tented both sides, 66 vias
v3: diameter 19.68, hole 7.87, Top Layer to Bottom Layer, 10 vias
v4: diameter 24, hole 12, Top Layer to Bottom Layer, tented both sides, 6 vias
v5: diameter 26, hole 13, Top Layer to Bottom Layer, tented both sides, 5 vias

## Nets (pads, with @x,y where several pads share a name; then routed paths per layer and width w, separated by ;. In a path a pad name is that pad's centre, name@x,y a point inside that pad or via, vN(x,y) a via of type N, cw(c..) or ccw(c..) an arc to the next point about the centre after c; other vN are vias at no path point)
"FOD THR": R23.1 R27.2 TP30.1 U1.35 | length 345.7
  Top Layer w8: U1.35@866.97,1350 1056,1350 R23.1@1063,1357
  Top Layer w10: R23.1@1067,1372 1127,1372 R27.2@1138,1361 ; R27.2@1132,1370 1135,1373 TP30.1@1135,1440
FOD_CAL: R22.1 R26.2 TP29.1 U1.10 | length 447.3
  Top Layer w10: U1.10@656.42,1477.13 656.42,1671.42 720,1735 720,1765 TP29.1@710,1775 ; TP29.1@715,1770 715,1780 703,1792 703,1835 R26.2@752,1835
GND: BUZ1.2 C1.1 C2.1 C13.2 C15.2 C21.2 C22.2 C23.1 C24.1 C25.1 C26.2 C27.1 C28.2 D1.2 D4.2 D5.2 D6.2 J4.1 J5.9 L2.4 NT1.1 NTC1.1 R2.1 R5.2 R7.1 R10.1 R14.1 R25.1 R26.1 R27.1 R28.1 R30.2 R31.2 R32.1 TP7.1 TP8.1 TP9.1 TP10.1 TP51.1 TP54.1 TP57.1 U1.31 U1.36 U1.39 U1.41 U2.5 U2.6 U2.13 U2.33 | length 1028.5
  Top Layer w10: U1.41@754.84,1364.84 745,1355 783.31,1316.69 U1.41@796.31,1316.69 ; 810,1295 833.58,1271.42 U1.31@859.17,1271.42 ; U1.36@856.97,1369.84 999.84,1369.84 v1(1010,1380) ; U1.36@856.97,1370 760,1370 818.9,1428.9 888.9,1428.9 912,1452 C22.2@920,1452 ; v1(875,1243) 877,1241 877,1227 981.5,1227 990,1218.5 ; 1065,1100 1113,1100 1145,1132 1145,1155 ; 1421.89,1390 1435.94,1404.06 U2.5@1450.41,1404.06 U2.6@1450.41,1384.37 ; v3(1544.9,1413.9) 1554.74,1404.06 U2.13@1554.74,1319.41
  Top Layer w15: v1(1410,1390) 1421.89,1390
  Top Layer w20: v1(1390,1375) 1405,1390 v1(1410,1390)
  other v1: 2500,100 440,285 2500,300 2500,500 1115,635 1310,635 1500,635 2500,700 2500,900 1285,930 1435,970 1435,995 2500,1100 900,1120 465,1180 921,1196 951,1196 265,1225 305,1265 1195,1280 2500,1300 440,1305 350,1315 1369,1315 375,1330 460,1340 430,1390 1195,1405 520,1440 948,1442 1265,1460 1295,1460 455,1465 485,1465 948,1466 455,1490 485,1490 2500,1500 455,1525 965,1590 555,1690 2500,1700 1055,1715 1456,1780 730,1889 2500,1900 1600,1905 607,1913 1620,1915 1605,1935 1385,1940 939,1950 1345,1965 939,1976 2500,2100 580,2270 2500,2300 2500,2500 300,2800 500,2800 2100,2800 2300,2800 2500,2800
  other v2: 206.33,44 406.33,44 606.33,44 806.33,44 1006.33,44 1206.33,44 1406.33,44 1606.33,44 1806.33,44 2006.33,44 2206.33,44 2406.33,44 100,300 3520,380 3875,380 4225,380 4645,380 5020,380 3160,395 2872,450 2765,465 100,500 5022,643 2765,665 100,700 2868,713 5022,863 2765,865 100,900 2868,929 2765,1065 100,1100 5022,1123 2867,1192 2765,1265 5022,1338 2867,1409 2765,1465 5022,1558 2867,1623 2765,1665 5017,1818 2765,1865 2867,1888 5017,2038 2765,2065 2867,2105 100,2200 5017,2253 2765,2265 2867,2316 100,2400 5017,2418 3185,2420 3610,2420 3960,2420 4315,2420 4730,2420 100,2600 700,2800 900,2800 1100,2800 1300,2800 1500,2800 1700,2800 1900,2800
  other v3: 745,1312.76 1544.9,1355.83 697.76,1360 745,1360 792.24,1360 745,1407.24 1486.83,1413.9 1602.97,1413.9 1544.9,1471.97
JTAG_CLK: J5.7 U1.19 | length 2168.8
  Top Layer w10: v1@495,1270 500,1265 555,1265 581.1,1291.1 U1.19@627.87,1291.1
  MidLayer2 w10: v1(495,1265) 380,1265 295,1180 295,1040 185,930 185,495 565,115 985,115 J5.7@1045,175 J5.7@1045,190
JTAG_DATA: C26.1 J5.1 R15.1 U1.20 | length 1995
  Top Layer w10: C26.1@438,177.5 R15.1@500,177.5 ; v1(495,1230) 558,1230 599.42,1271.42 U1.20@627.87,1271.42 ; R15.1@505,177.5 J5.1@742.5,177.5 ; J5.1@742.5,192.5 J5.1@745,190
  MidLayer2 w10: v1(495,1230) 380,1230 320,1170 320,1020 220,920 220,560 605,175 730,175 J5.1@745,190
"LED MODE": R21.1 R25.2 TP27.1 U1.34 | length 358.1
  Top Layer w9: U1.34@862.13,1330.47 1017.53,1330.47 1035,1313 R25.2@1135,1313
  Top Layer w10: TP27.1@1135,1235 R25.2@1135,1313
NetBUZ1_1: BUZ1.1 R28.2 TP23.1 U1.15 | length 967.6
  Top Layer w10: v1(265,1100) 265,1072 R28.2@263,1070 ; BUZ1.1@290,768.43 290,960 263,987 R28.2@263,1070 ; TP23.1@345,1070 R28.2@263,1070 ; v1@515,1385 530,1385 545.16,1369.84 U1.15@627.87,1369.84
  MidLayer2 w10: v1(265,1100) 265,1185 465,1385 v1(520,1385)
NetC2_2: C2.2 C4.1 C5.2 C6.1 C7.2 R18.2 U2.14 U2.15 U2.27 U2.28
  other v1: 1580,1085 1605,1085 1629,1085 1591,1106 1619,1106 1730,1785 1670,1845 1670,1875 1670,1905 1670,1935 1730,1960 1670,1995 1670,2025 1670,2080
NetC3_1: C3.1 R18.3 TP1.1 U2.30 | length 586.3
  Top Layer w10: TP1.1@1440,1855 1496,1855 1496,1848 C3.1@1497,1847 ; 1514.35,1538 1515.37,1536.98
  Top Layer w11: U2.30@1515.37,1508.39 1515.37,1536.98
  Top Layer w15: C3.1@1493,1850 1514.35,1828.65 1514.35,1538 ; C3.1@1497,1847 R18.3@1497,2018
NetC3_2: C3.2 R11.1 TP2.1 U2.29 | length 463.1
  Top Layer w10: U2.29@1535.05,1514.05 1535,1828.99 C3.2@1553,1847 ; R11.1@1557,1904 1552,1904 1552,1848 C3.2@1553,1847 ; TP2.1@1610,1855 1561,1855 C3.2@1553,1847
NetC8_1: C8.1 J1.1 J1.2 J2.1 L2.2 R3.1 TP3.1
NetC8_2: C8.2 J2.5 J3.1 J3.2 L2.3 R5.1 TP4.1
NetC9_1: C9.1 R6.1 R7.2 | length 139
  Top Layer w10: C9.1@1375,873.5 C9.1@1380,873.5 ; R6.1@1380,793 C9.1@1380,872 C9.1@1380,873.5 ; C9.1@1380,877 C9.1@1380,873.5 ; R7.2@1430,873.5 C9.1@1380,873.5
NetC9_2: C9.2 TP5.1 U2.11 | length 446.6
  Top Layer w10: C9.2@1380,928 1380,1000 TP5.1@1375,1005 1375,1070 1515.9,1210.9 1515.9,1313.4 U2.11@1515.35,1313.95
NetC10_1: C10.1 C11.2 L1.1 TP6.1 U2.23 U2.24 U2.26 | length 82.5
  Top Layer w10: U2.26@1594.15,1514.05 1594.15,1574.15 1610,1590
NetC10_2: C10.2 R8.2 | length 157.9
  Top Layer w30: C10.2@1762,1484 1786,1508 R8.2@1910,1508
NetC11_1: C11.1 U2.25 | length 64.4
  Top Layer w11.5: U2.25@1613.85,1514.05 1613.85,1518.85 C11.1@1656,1561
NetC12_1: C12.1 C15.1 D3.1 R10.2 | length 378.4
  Top Layer w10: C15.1@1480,872 1524,872 1580,928 1580,965 1563,982 1530,982 1480,1032 R10.2@1480,1038 ; C15.1@1480,873.5 C15.1@1480,877
  Top Layer w15: C15.1@1480,872 1480,845 1501.69,823.31 D3.1@1501.69,800
NetC12_2: C12.2 TP12.1 U2.12 | length 311.7
  Top Layer w10: TP12.1@1505,1150 1505,1140 TP12.1@1510,1145 ; C12.2@1530,1038 1530,1085 1510,1105 TP12.1@1510,1145 ; U2.12@1535.05,1313.95 1535,1313.9 1535,1200 1510,1175 TP12.1@1510,1145
NetC13_1: C13.1 D2.1 R1.2 | length 143.8
  Top Layer w10: R1.2@1175,816.5 1186.5,805 1290,805 D2.1@1307,822
NetC14_2: C14.2 C16.2 C17.2 C18.1 C19.2 C20.1 TP14.1 U2.17 U2.18 U2.19
NetC18_2: C18.2 R16.2 | length 60.1
  Top Layer w30: C18.2@1759,1362 1805,1362 R16.2@1815,1352
NetC20_2: C20.2 U2.16 | length 69
  Top Layer w11.5: U2.16@1613.85,1313.95 1613.85,1303.15 C20.2@1655,1262
NetC23_2: C23.2 TP20.1 U1.3 U2.31 | length 915.4
  Top Layer w10: U1.3@794.21,1477.13 794.21,1529.21 v1(855,1590) 882,1590 882,1592 TP20.1@917.5,1627.5 ; v1(1438,1570) 1454,1570 1496,1528 U2.31@1496,1509
  MidLayer2 w10: v1(855,1590) 890,1555 1423,1555 v1(1438,1570)
NetC25_2: C25.2 U1.30 | length 77.3
  Top Layer w10: U1.30@833.58,1237.87 833.58,1204.42 860,1178 C25.2@860,1171.5
NetD1_1: D1.1 R4.1 | length 70.6
  Top Layer w10: D1.1@485.47,2270 485.47,2201.53 R4.1@487,2200
NetD4_1: D4.1 R17.1 | length 65.5
  Top Layer w10: R17.1@1106,2314 D4.1@1171.47,2314
NetD5_1: D5.1 R9.1 | length 55.5
  Top Layer w10: R9.1@1106,2245 D5.1@1161.47,2245
NetD6_1: D6.1 R19.1 | length 54.9
  Top Layer w10: R19.1@1106,2175 1107,2174 D6.1@1160.47,2174
NetR9_2: R9.2 TP24.1 U1.12 | length 1141.2
  Top Layer w10: v1@595,1500 595,1440 606.1,1428.9 U1.12@627.87,1428.9 ; TP24.1@885,2243 887,2245 v1(940,2245) ; v1@935,2245 v1(940,2245) ; R9.2@1040,2245 v1(940,2245)
  MidLayer2 w10: v1(595,1505) 595,1630 883,1918 883,2188 v1(940,2245)
NetR11_2: R11.2 R18.4 | length 62.4
  Top Layer w10: R11.2@1560,1963 1560,1998.31 R18.4@1579.13,2017.44
NetR17_2: R17.2 TP26.1 U1.14 | length 1333.4
  Top Layer w10: v1@540,1405 v1(545,1405) 560.47,1389.53 U1.14@627.87,1389.53 ; TP26.1@885,2315 886,2314 v1(940,2314) R17.2@1050,2314
  MidLayer2 w10: v1@540,1405 545,1410 545,1625 855,1935 855,2228 v1@940,2313
NetR19_2: R19.2 TP25.1 U1.11 | length 1018.1
  Top Layer w10: v1@625,1500 627.87,1497.13 U1.11@627.87,1448.58 ; TP25.1@885,2175 v1(940,2175) R19.2@1050,2175
  MidLayer2 w10: v1@625,1505 628,1508 628,1613.17 910,1895.17 910,2145 v1(940,2175)
  other v1: 628,1505
NetR29_2: R29.2 R32.2 TP33.1 U1.4 | length 736.2
  Top Layer w10: U1.4@774.53,1474.17 774.53,1564.53 820,1610 820,1650 940,1770 R32.2@1020,1770 ; R32.2@1010,1773 1013,1770 1145,1770 TP33.1@1255,1880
